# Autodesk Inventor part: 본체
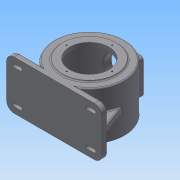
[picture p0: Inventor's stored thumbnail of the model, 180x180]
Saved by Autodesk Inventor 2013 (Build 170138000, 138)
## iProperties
Created: 2015-06
Part Number: 본체
Material: 일반
Document SubType Name: Modeling
Designer: Administrator
Density: 1 g/cm^3
Author: Administrator
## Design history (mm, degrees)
sketch "스케치1"
  geometry: L1 (-115, 59)-(115, 59); L2 (115, 59)-(115, -59); L3 (115, -59)-(-115, -59); L4 (-115, -59)-(-115, 59); 3 further points
  constraints: 8 end point, 2 midpoint, 2 parallel, 1 horizontal, 1 horizontal alignment, 1 perpendicular, 1 vertical alignment
  dimensions: "d0" = 230 distance of L1.start L1.end; "d2" = 118 distance of L3.end L1.start
extrude "돌출1" new body sketch "스케치1" stored distance "d3" = 14; taper "d4" = 0 deg
node "작업 평면1"
sketch "스케치10"
  geometry: L1 (230, -14)-(0, -14) reference; C1 r 85 at (115, 71); 1 further point
  constraints: 1 centre point, 1 vertical alignment
  dimensions: "d79" = 170 diameter of C1; "d81" = 85 distance from line of L1 C1.centre
extrude "돌출7" join sketch "스케치10" distance "d82" = 118; taper "d83" = 0 deg
node "작업 평면3"
sketch "스케치11"
  geometry: L1 (46.733, -59)-(46.733, 59) reference; L2 (46.733, -59)-(-46.733, -59) reference; L3 (-46.733, 59)-(-46.733, -59) reference; L4 (46.733, 59)-(-46.733, 59) reference; L5 (-35.5, -42.5)-(35.5, -42.5); L6 (42.5, -35.5)-(42.5, 35.5); L7 (35.5, 42.5)-(-35.5, 42.5); L8 (-42.5, 35.5)-(-42.5, -35.5); A1 r 7 centre (-35.5, -35.5) between (-42.5, -35.5) and (-35.5, -42.5); A2 r 7 centre (35.5, -35.5) between (35.5, -42.5) and (42.5, -35.5); A3 r 7 centre (35.5, 35.5) between (42.5, 35.5) and (35.5, 42.5); A4 r 7 centre (-35.5, 35.5) between (-35.5, 42.5) and (-42.5, 35.5); 7 further points
  constraints: 8 end point, 8 point on circle, 8 point on line, 8 tangent, 4 centre point, 3 equal radius, 2 midpoint, 2 parallel, 1 horizontal, 1 horizontal alignment, 1 perpendicular, 1 vertical alignment
  dimensions: "d85" = 85 distance of point (-42.5, -42.5) point (42.5, -42.5); "d87" = 85 distance of point (42.5, -42.5) point (42.5, 42.5); "d180" = 7 radius of A1
extrude "돌출8" join sketch "스케치11" stored distance "d88" = 118; taper "d89" = 0 deg
sketch "스케치12"
  geometry: 1 further point
sketch "스케치13"
  geometry: C1 r 65 at (115, 85); A1 r 85 centre (115, 85) between (161.733, 14) and (68.267, 14) reference; 1 further point
  constraints: 1 centre point, 1 coincident
  dimensions: "d90" = 130 diameter of C1
extrude "돌출9" join sketch "스케치13" distance "d92" = 13; taper "d93" = 0 deg
sketch "스케치14"
  geometry: C1 r 65 at (115, 85); A1 r 85 centre (115, 85) between (161.733, 14) and (68.267, 14) reference; 1 further point
  constraints: 1 centre point, 1 coincident
  dimensions: "d94" = 130 diameter of C1
extrude "돌출10" join sketch "스케치14" distance "d96" = 3; taper "d97" = 0 deg
sketch "스케치17" dims "d176" = 0.3
  geometry: L1 (-7, -59)-(-7, 59) reference; L2 (-7, 59)-(13, 59) reference; L3 (13, 59)-(13, 62) reference; L4 (13, 62)-(143, 62) reference; L5 (143, 62)-(143, 59) reference; L6 (143, 59)-(163, 59) reference; L7 (163, 59)-(163, 42.5) reference; L8 (163, 42.5)-(166, 42.5) reference; L9 (166, 42.5)-(166, -42.5) reference; L10 (166, -42.5)-(163, -42.5) reference; L11 (163, -42.5)-(163, -59) reference; L12 (163, -59)-(143, -59) reference; L13 (143, -59)-(143, -72) reference; L14 (143, -72)-(13, -72) reference; L15 (13, -72)-(13, -59) reference; L16 (13, -59)-(-7, -59) reference; L17 (125.5, 62)-(125.5, 51); L18 (78, -72)-(78, 62); L19 (125.5, 51)-(155, 51); L20 (155, 51)-(155, -51); L21 (155, -51)-(109, -51); L22 (109, -51)-(107.368, -47.5); L23 (107.368, -47.5)-(101.5, -47.5); L24 (101.5, -47.5)-(101.5, -61.5); L25 (101.5, -61.5)-(93, -61.5); L26 (93, -61.5)-(93, -64.5); L27 (93, -64.5)-(78, -64.5); 1 further point
  constraints: 22 end point, 5 perpendicular, 4 parallel, 2 midpoint, 2 point on line
  dimensions: "d101" = 95 diameter of L17 L18; "d103" = 154 diameter of L20 L18; "d104" = 102 distance of L19.end L20.end; "d105" = 11 distance of L17.start L17.end; "d107" = 3.5 distance from line of L21 L22.end; "d108" = 115 deg angle of L21 L22; "d109" = 62 diameter of L21.end L18; "d110" = 14 distance of L23.end L24.end; "d111" = 47 diameter of L24 L18; "d112" = 30 diameter of L25.end L18; "d113" = 3 distance between parallel lines of L25 L27
revolve "회전2" sketch "스케치17" stored, may be unused: angle "d114" = 90 deg
sketch "스케치18"
  geometry: C1 r 35 at (0, 0); 1 further point
  constraints: 1 centre point, 1 coincident
  dimensions: "d115" = 70 diameter of C1
extrude "돌출11" cut sketch "스케치18" stored distance "d117" = 3; taper "d118" = 0 deg
sketch "스케치19"
  geometry: C1 r 35 at (0, 0) reference; 4 further points
  dimensions: "d119" = 35.5 horizontal distance of point (-35.5, 35.5) C1.centre; "d120" = 35.5 horizontal distance of C1.centre point (-35.5, 35.5); "d121" = 35.5 horizontal distance of point (-35.5, -35.5) C1.centre; "d122" = 35.5 horizontal distance of C1.centre point (-35.5, -35.5); "d123" = 35.5 horizontal distance of C1.centre point (35.5, -35.5); "d124" = 35.5 horizontal distance of C1.centre point (35.5, -35.5); "d125" = 35.5 horizontal distance of C1.centre point (35.5, 35.5); "d126" = 35.5 horizontal distance of C1.centre point (35.5, 35.5)
hole "구멍4" sketch "스케치19" at (-35.5, -35.5), (35.5, -35.5), (35.5, 35.5), (-35.5, 35.5) diameter "d127" = 3.242; stored, may be unused: countersink angle "d131" = 90 deg, drill point angle "d133" = 118 deg; dims "d128" = 10, "d129" = 4, "d130" = 2, "d132" = 13
sketch "스케치20"
  geometry: C1 r 65 at (0, 0) reference; 2 further points
  constraints: 1 vertical alignment
  dimensions: "d134" = 55 distance of C1.centre point (0, 55)
hole "구멍5" sketch "스케치20" at (0, 55) diameter "d135" = 3.242; stored, may be unused: countersink angle "d139" = 90 deg, drill point angle "d141" = 118 deg; dims "d136" = 10, "d137" = 4, "d138" = 2, "d140" = 13
sketch "스케치21"
  geometry: L1 (-46.733, 59)-(-115, 59) reference; L2 (-115, -59)-(-46.733, -59) reference; L3 (-81, 50)-(-97, 50); L4 (-97, 32)-(-81, 32); L5 (-46.733, -59)-(-46.733, 59) reference; L6 (-46.733, 59)-(-115, 59) reference; L7 (-115, 59)-(-115, -59) reference; L8 (-115, -59)-(-46.733, -59) reference; A1 r 9 centre (-97, 41) between (-97, 50) and (-97, 32); A2 r 9 centre (-81, 41) between (-81, 32) and (-81, 50); 1 further point
  constraints: 4 end point, 4 point on circle, 4 tangent, 2 centre point, 2 parallel
  dimensions: "d145" = 18 distance between parallel lines of L3 L4; "d146" = 18 distance from line of L1 A1.centre; "d147" = 16 distance of A1.centre A2.centre; "d148" = 97 horizontal distance of A1.centre point (0, 0)
extrude "돌출12" join sketch "스케치21" distance "d149" = 3; taper "d150" = 0 deg
sketch "스케치22"
  geometry: L1 (-81, 50)-(-97, 50) reference; L2 (-97, 32)-(-81, 32) reference; L3 (-97, 45)-(-81, 45); L4 (-81, 37)-(-97, 37); A1 r 9 centre (-97, 41) between (-97, 50) and (-97, 32) reference; A2 r 9 centre (-81, 41) between (-81, 32) and (-81, 50) reference; A3 r 4 centre (-81, 41) between (-81, 37) and (-81, 45); A4 r 4 centre (-97, 41) between (-97, 45) and (-97, 37); 1 further point
  constraints: 4 end point, 4 point on circle, 2 centre point, 3 other
  dimensions: "d151" = 8 distance between parallel lines of L4 L3
extrude "돌출13" cut sketch "스케치22" stored distance "d153" = 3; taper "d154" = 0 deg
node "작업 평면4"
sketch "스케치23"
  geometry: L1 (230, 0)-(0, 0) reference; L2 (0, 0)-(0, 14) reference; L3 (0, 14)-(68.267, 14) reference; L4 (72.5, 158.612)-(72.5, 173) reference; L5 (72.5, 173)-(80, 173) reference; L6 (80, 173)-(80, 153.586) reference; L7 (150, 153.586)-(150, 173) reference; L8 (150, 173)-(157.5, 173) reference; L9 (157.5, 173)-(157.5, 158.612) reference; L10 (161.733, 14)-(230, 14) reference; L11 (230, 14)-(230, 0) reference; L12 (199.87, 80.297)-(224, 14); L13 (6, 14)-(30.13, 80.297); A1 r 85 centre (115, 85) between (72.5, 158.612) and (68.267, 14) reference; A2 r 77 centre (115, 85) between (80, 153.586) and (150, 153.586) reference; A3 r 85 centre (115, 85) between (161.733, 14) and (157.5, 158.612) reference; 1 further point
  constraints: 4 end point, 2 point on circle, 2 point on line
  dimensions: "d156" = 6 distance of L10.end L12.end; "d157" = 110 deg angle of L12 L10; "d158" = 6 distance from line of L13.start L2; "d159" = 110 deg angle of L13 L3
  node "절단 모서리 투영4"
feature "리브1" dims "d160" = 1, "d161" = 15, "d162" = 0, "d163" = 0, "d164" = 1, "d165" = 1
feature "리브2" dims "d166" = 1, "d167" = 15, "d168" = 0, "d169" = 0, "d170" = 1, "d171" = 1
sketch "스케치24"
  geometry: 1 further point
fillet "모깎기1" dims "d172" = 18
fillet "모깎기2" dims "d173" = 3
fillet "모깎기4" dims "d175" = 3
fillet "모깎기5" dims "d176" = 0.3
fillet "모깎기6" dims "d177" = 3
fillet "모깎기7" dims "d178" = 1
chamfer "모따기1" distance "d181" = 1; stored, may be unused: second distance "d182" = 2, angle "d183" = 45 deg
fillet "모깎기8" dims "d184" = 3
fillet "모깎기9" dims "d185" = 3
fillet "모깎기10" dims "d186" = 3
fillet "모깎기11" dims "d187" = 3
node "솔리드1"
pattern_circular "원형 패턴2" dims angle "d143" = 360 deg
mirror "대칭1"
mirror "대칭2"
node "투영된 루프2"
node "투영된 루프3"
node "절단 모서리 투영3"
other parameters: "d5" = -8, "d84" = -173, "d155" = -59
